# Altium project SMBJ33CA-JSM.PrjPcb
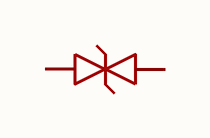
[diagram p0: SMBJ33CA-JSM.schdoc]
1 sheet, 1 parts. Net scope: global (net labels, ports and power ports of the same name join across sheets).

## Sheet SMBJ33CA-JSM.schdoc
size 127 x 101 mm

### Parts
D?  smbj33ca-jsm  [SMB_L4.4-W3.6-LS5.3-BI]  (value not drawn)

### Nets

Not connected (* = marked no-connect by the designer): D? 1 2

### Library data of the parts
D? = smbj33ca-jsm: 极性:双向;反向截止电压(Vrwm):33V;钳位电压:53.3V;峰值脉冲电流(Ipp):11.3A;峰值脉冲功率(Ppp):600W@10/1000us;击穿电压(VBR):40.6V;; Manufacturer: JSMSEMI(杰盛微); AddInBom: yes; ModelId: 0b05f1e84232498d868b1eafe1bb2917; ModelTransform: 210.2358,142.3979,0,0,0,0,0,0,0; Polarity: 双向; Reverse Stand-Off Voltage (Vrwm): 33V; Clamping Voltage: 53.3V; Peak Pulse Current (Ipp): 11.3A; Voltage - Breakdown: 40.6V; Reverse Leakage Current (Ir): 1uA; Number of Channels: 单路; Type: TVS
